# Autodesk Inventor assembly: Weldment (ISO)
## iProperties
Length Units: 11269
Angle Units: 11283
Time Units: 11279
Mass Units: 11290
Length Display Precision: 3
Angle Display Precision: 2
Part Number: Weldment (ISO)
Document SubType Name: Weldment
Created: 2002-06
Designer: smithga
Part Number: Ens_extension_reduction
Created: 2008-04
Designer: plup
Material: Aluminum soudé-6061
Control State: 0
Master: False
Shininess: 64.0
Angle Units: 11279
Time Units: 11290
Mass Units: 11283
Compacted: True
DESIGNATION: Ensemble extension
Density: 0.0
Volumn: 0.0
Area: 0.0
PropertySet Name: Model Information
Author: plup
